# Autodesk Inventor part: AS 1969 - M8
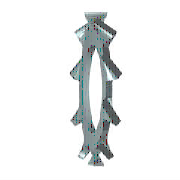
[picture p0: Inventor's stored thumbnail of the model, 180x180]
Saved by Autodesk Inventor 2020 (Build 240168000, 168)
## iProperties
IsCustomPart: 0
Created: 2008-02
Part Number: AS 1969 - M8
Material: Steel, Mild
Description: Metric Tooth LW
Document SubType Name: Modeling
Standard: AS 1969
Designer: PN
Standards Organization: AS
Language: en-US
Size Designation: M8
Categories: <MemberInstance><Categories><Category DisplayName="Fasteners" InternalName="e4da775c-781d-43d5-af7c-5136215cf5a6" Mnemonic="FSTN"><Category DisplayName="Washers
Density: 7.86 g/cm^3
Mass: 0.474048 g
Surface Area: 2.15852 cm^2
Volume: 0.0603114 cm^3
Appearance: Steel
Author: PN
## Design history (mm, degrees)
sketch "Sketch1"
  geometry: C1 r 7 at (0, 0); C2 r 4.2 at (0, 0)
  constraints: 2 centre point, 1 coincident, 1 other
  dimensions: "d0" = 14 diameter of C1 (= SD2); "d1" = 8.4 diameter of C2 (= SD1)
extrude "Body" new body sketch "Sketch1" distance "d2" = 0.85 (= SD); taper "d3" = 0 deg
sketch "Sketch2"
  geometry: L1 (0, 0)-(0, 7); L2 (-1.093, 5.492)-(-1.366, 6.865); L3 (1.093, 5.492)-(1.366, 6.865); L4 (-1.093, 5.492)-(0, 0); L5 (0, 0)-(1.093, 5.492); A1 r 7 centre (0, 0) between (0, 7) and (1.366, 6.865) reference; A2 r 7 centre (0, 0) between (1.366, 6.865) and (-1.366, 6.865); A3 r 5.6 centre (0, 0) between (1.093, 5.492) and (-1.093, 5.492)
  constraints: 10 end point, 7 point on circle, 2 centre point, 2 coincident, 2 collinear, 1 concentric, 1 symmetric about line, 1 vertical
  dimensions: "d4" = 22.5 deg angle of L3 L2 (computed from SAZ); "d5" = 11.2 diameter of A3 (= 0.5 x SD2 + 0.5 x SD1)
extrude "Cut" cut sketch "Sketch2" extent not by distance; stored distance "d6" = 0.85 (= SD); taper "d7" = 0 deg
pattern_circular "Cuts" dims angle "d11" = 360 deg
workaxis "Work Axis1"
workplane "Work Plane1"
body "Solid1"
fillet "Fillet1" dims "d8" = 0.21 (= 0.015 x SD2)
other parameters: "SD" = 0.85 [user parameter; used in 2 equation terms], "SD1" = 8.4 [user parameter; used in 2 equation terms], "SD2" = 14 [user parameter; used in 3 equation terms], "NND" = 8 [user parameter], "d12" = 0, "d13" = 0, "d14" = 0, "d15" = 0, "d16" = 90 deg
